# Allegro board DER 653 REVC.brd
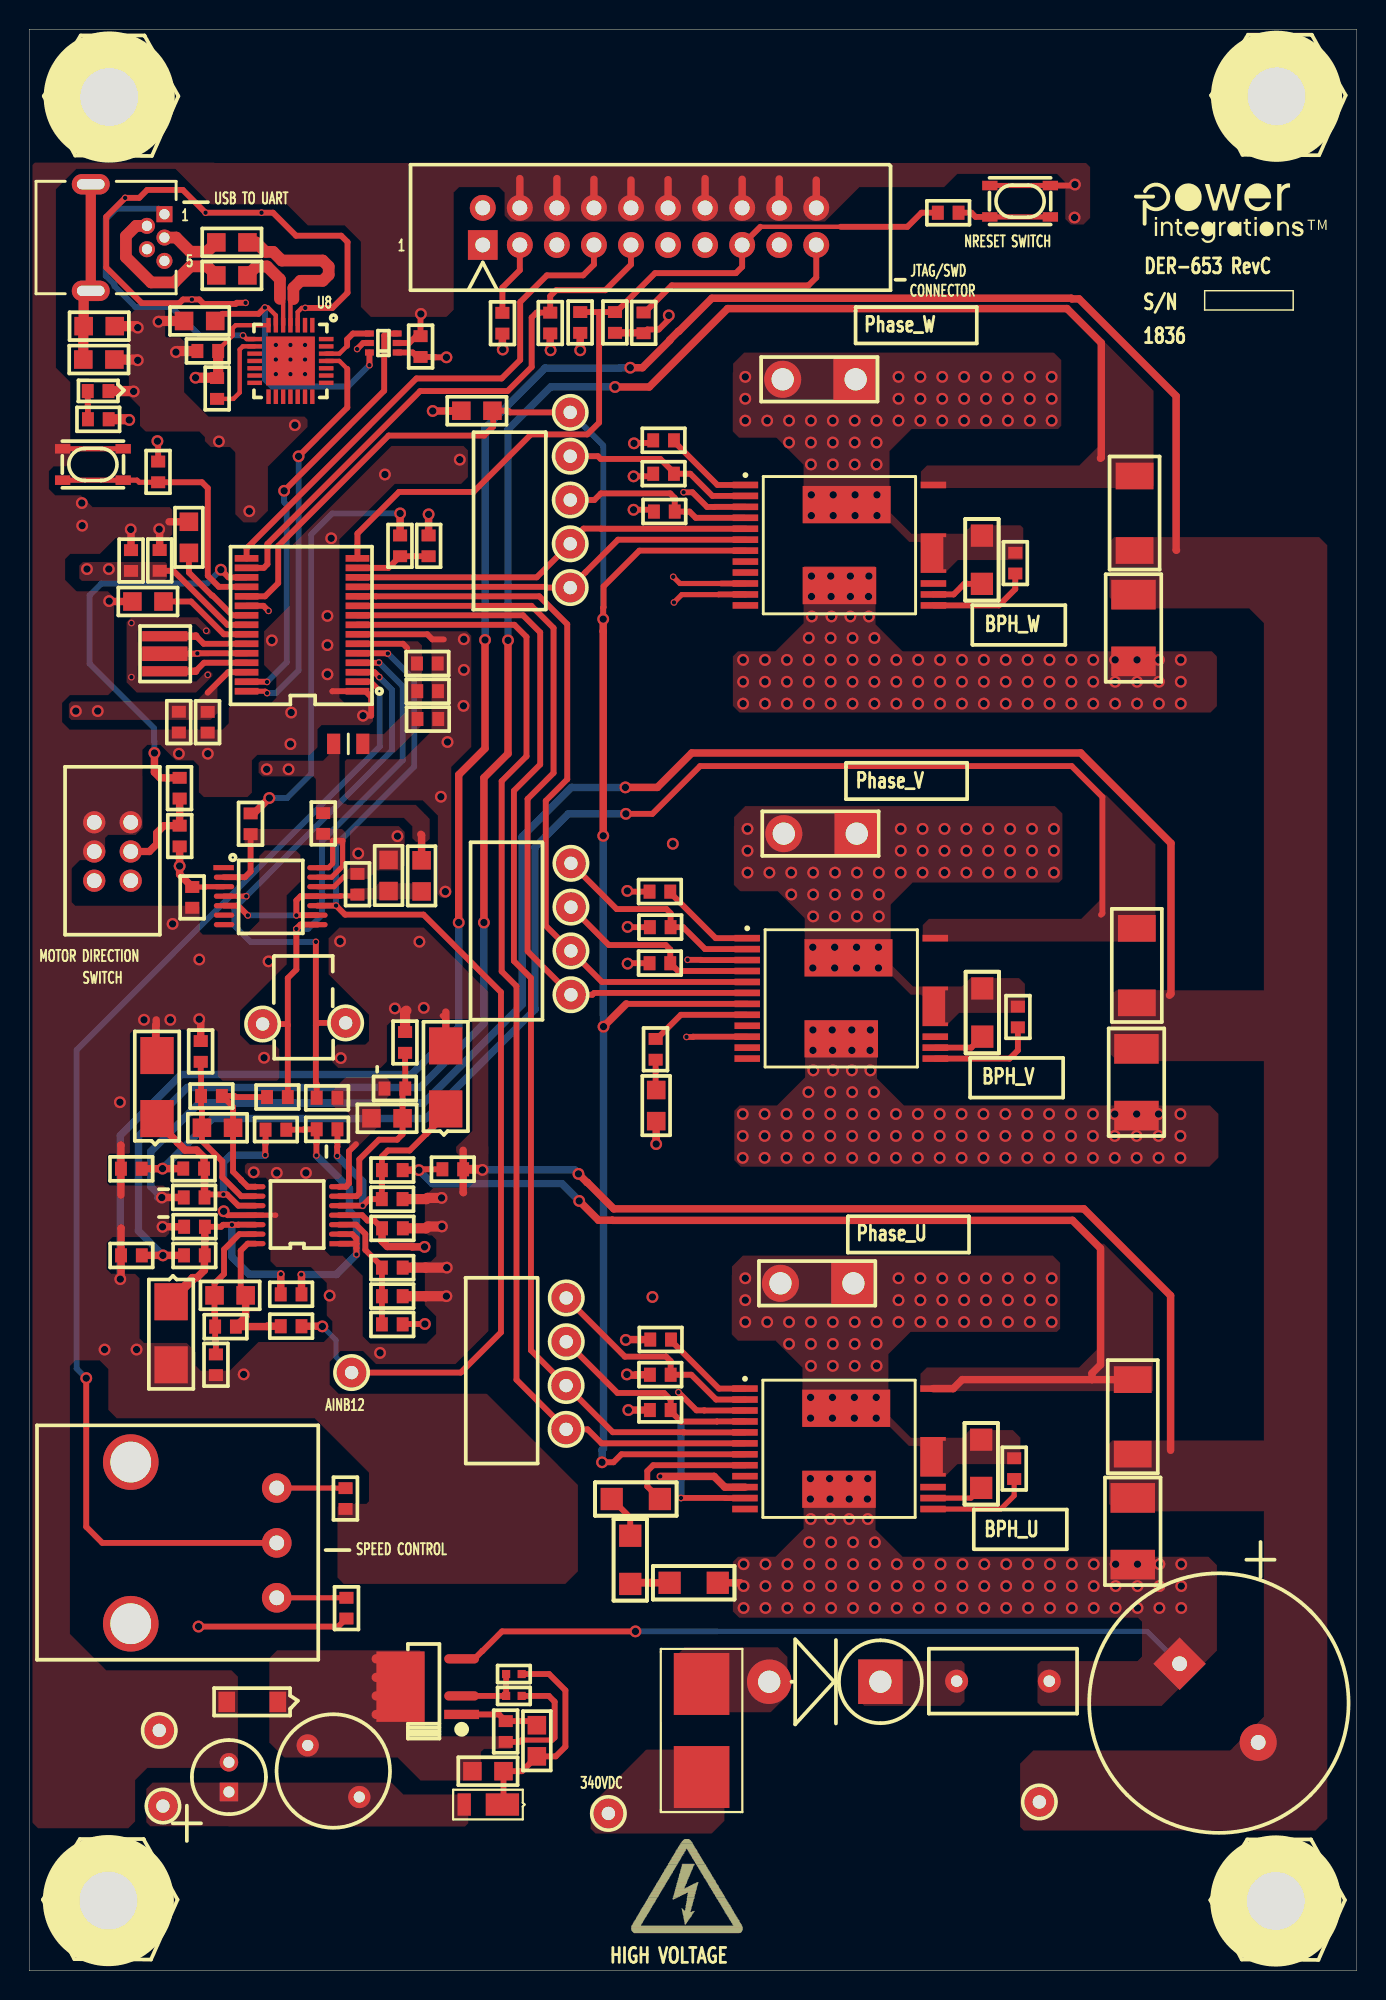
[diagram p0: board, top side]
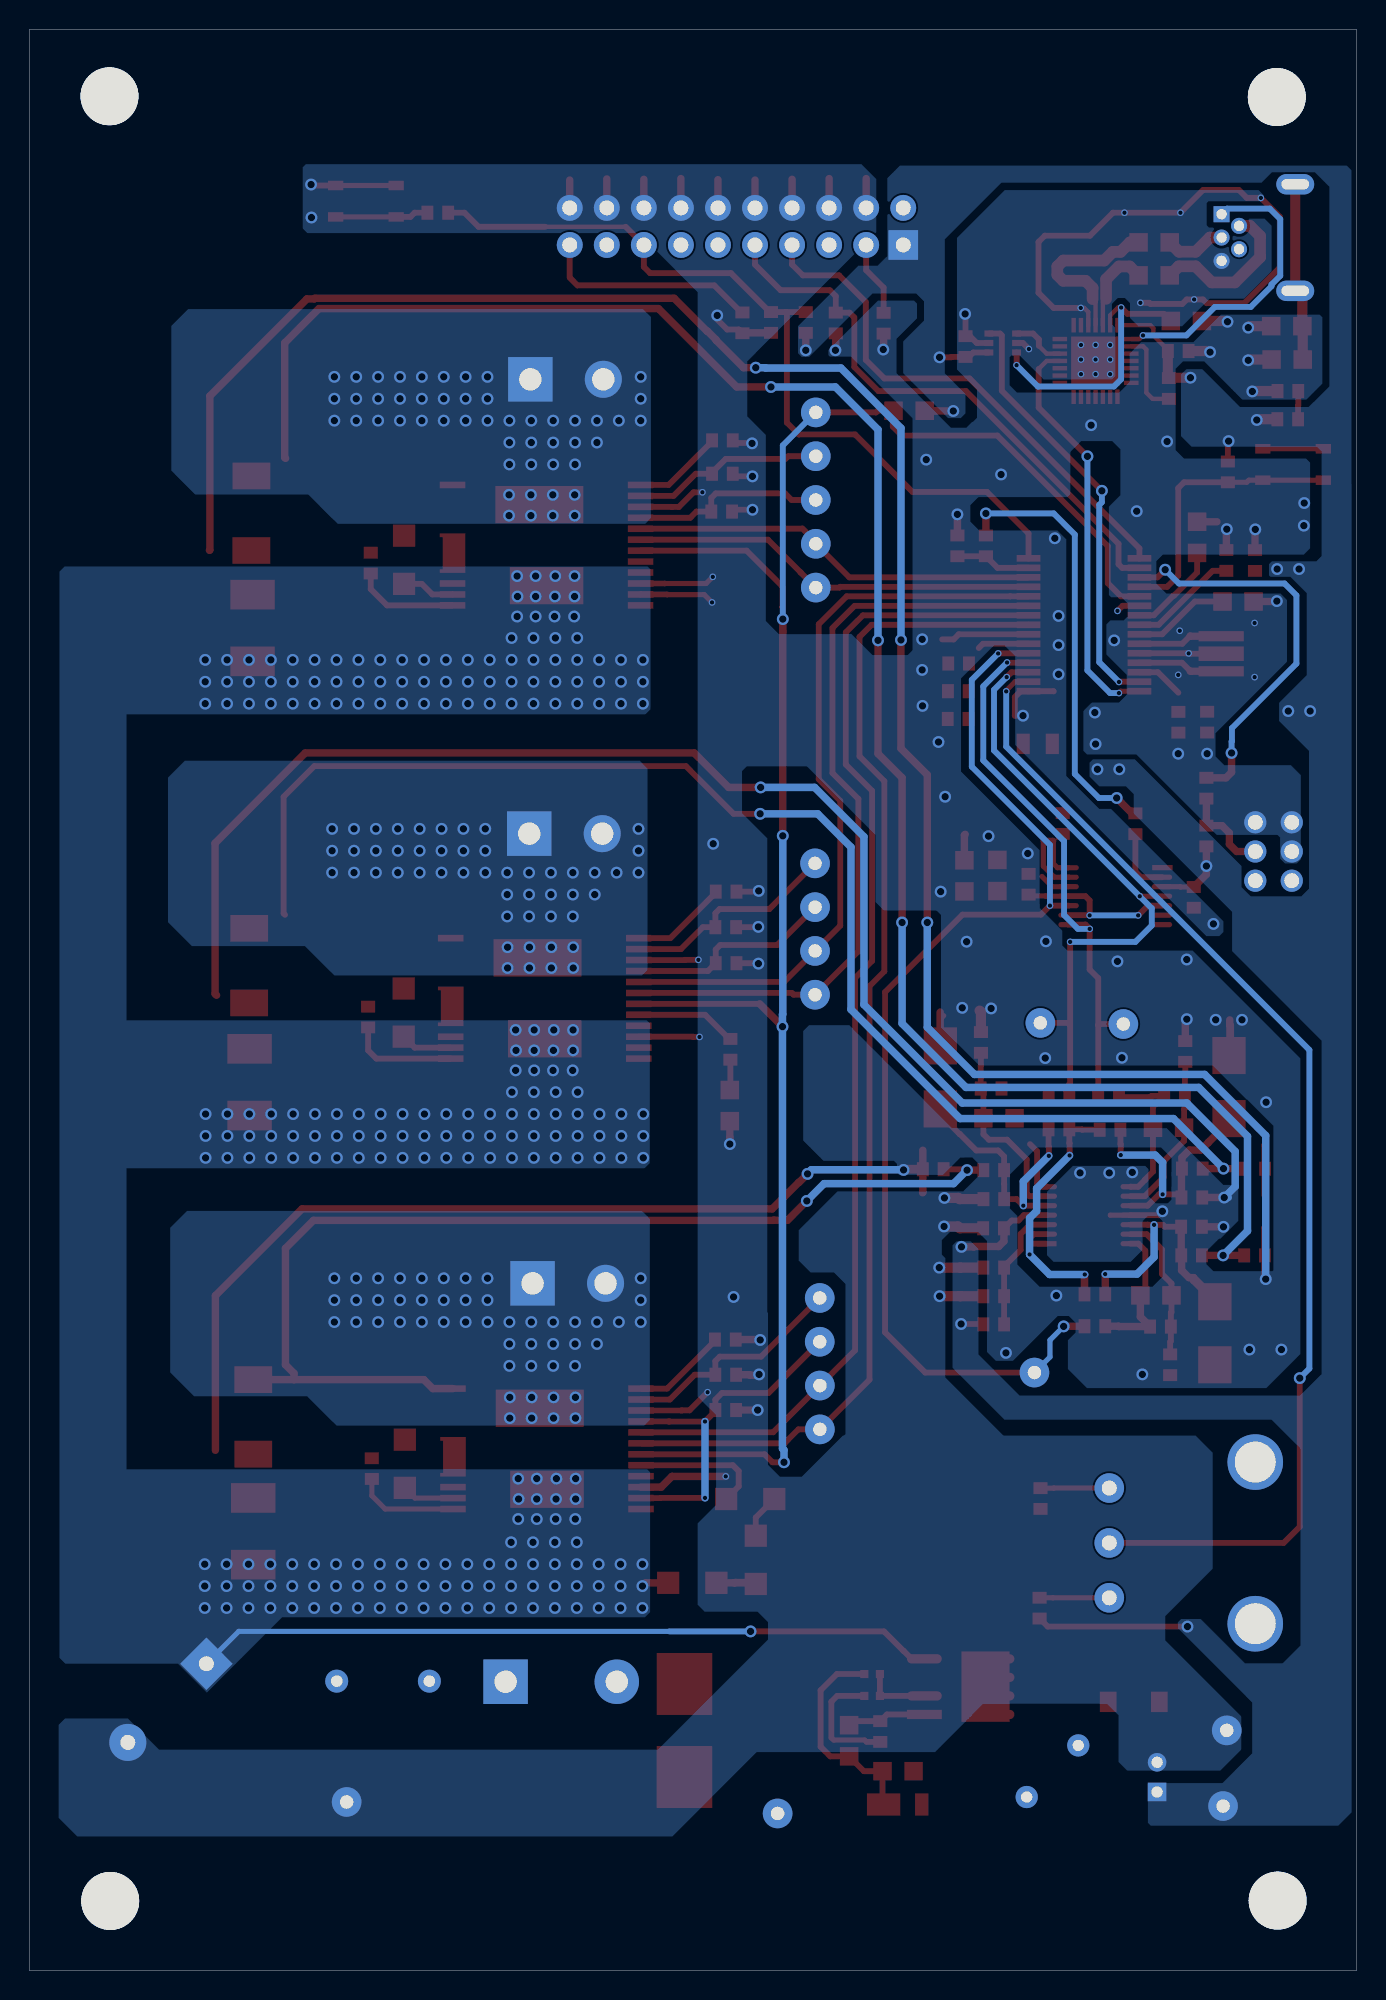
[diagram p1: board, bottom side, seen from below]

Outline 91 x 133 mm; copper layers: TOP, BOTTOM. Coordinates in mm from the lower left corner of the outline.
Outline path: 0,133 91,133 91,0 0,0 0,133

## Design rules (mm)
constraint set DEFAULT: min track width 0.35

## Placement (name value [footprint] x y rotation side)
AINB10  CON1  [PI_MILLMAX030D]  21.69 64.93 0 top
AINB11  CON1  [PI_MILLMAX030D]  16 64.85 0 top
AINB12  CON1  [PI_MILLMAX030D]  22.1 40.98 0 top
BPL_U  CON1  [PI_MILLMAX030D]  36.81 43.09 0 top
BPL_V  CON1  [PI_MILLMAX030D]  37.13 72.86 0 top
BPL_W  CON1  [PI_MILLMAX030D]  37.08 100.75 0 top
C1  100 pF  [PISMC0805]  23.46 58.4 0 top
C2  220 nF  [PISMC1812]  75.64 27.82 90 top
C3  4.7 uF  [PISMC1206]  65.25 33.08 90 top
C4  1000 pF  [PISMC0603]  29.75 54.9 180 top
C5  470 pF  [PISMC0603]  24.17 52.86 0 top
C6  1 nF  [PISMC0603]  8.94 95.9 90 top
C7  100 nF  [PISMC0603]  6.98 95.89 90 top
C8  100 pF  [PISMC0805]  13.97 57.75 180 top
C9  4.7uF  [PISMC0603]  26.62 85.75 0 top
C10  1 nF  [PISMC0603]  26.58 89.55 0 top
C11  100 nF  [PISMC0603]  26.6 87.65 0 top
C12  4.7 uF  [PISMC0805]  9.21 93.8 180 top
C13  1 nF  [PISMC0603]  12.23 86.24 270 top
C14  100 nF  [PISMC0603]  10.26 86.25 270 top
C15  1000 pF  [PISMC0603]  6.29 54.94 0 top
C16  1 uF  [PISMC0603]  43.97 38.41 180 top
C17  4.7 uF  [PISMC0805]  10.95 97.13 90 top
C18  470 pF  [PISMC0603]  12.02 52.97 180 top
C19  10 nF  [PISMC0603]  27.38 96.9 90 top
C20  100 pF  [PISMC0805]  14.84 46.27 180 top
C21  220 nF  [PISMC1812]  75.69 89.7 90 top
C22  4.7 uF  [PISMC1206]  65.33 63.99 90 top
C23  1000 pF  [PISMC0603]  6.3 49.01 0 top
C24  47 uF  [PIPOLCAPCLYD710LS300040]  78.85 21.03 315 top
C25  470 pF  [PISMC0603]  12.04 50.97 180 top
C26  1 uF  [PISMC0603]  43.94 69.02 180 top
C27  100 nF  [PISMC0603]  40.15 113.62 270 top
C28  1 uF  [PISMC0603]  24.18 48.17 0 top
C29  100 nF  [PISMC0603]  32.66 17.1 270 top
C30  10 uF  [PISMC0805]  32.51 13.67 180 top
C31  100 nF  [PISMC0603]  24.19 50.86 0 top
C32  220 nF  [PISMC1812]  75.9 58.58 90 top
C33  100 uF  [PIPOLCAPCLYD200LS80030]  13.69 12.25 90 top
C34  4.7 uF  [PISMC1206]  65.3 95 90 top
C35  100 nF  [PISMC0603]  11.18 74.24 270 top
C36  1 uF  [PISMC0603]  44.25 99.96 180 top
C37  4.7 uF  [PISMC0805]  3.73 112.66 0 top
C38  100 nF  [PISMC0603]  26.82 110.55 90 top
C39  4.7 uF  [PISMC0805]  10.62 113.01 0 top
C40  1 uF  [PISMC0603]  12.95 110.96 180 top
C41  1 uF  [PISMC0603]  22.5 73.72 90 top
D1  Green  [PI_SM_D_0603]  5.44 108.21 180 top
D2  SS13-E3/61T  [PISMDO214AC12]  28.55 59.04 90 top
D3  SS13-E3/61T  [PISMDO214AC12]  8.76 58.38 90 top
D4  1N5404-E3/54  [PIDV300X200X060DO15D0201AD]  58.34 19.8 180 top
D5  SS13-E3/61T  [PISMDO214AC12]  9.73 45.83 270 top
D6  DFLR1600-7  [PISMDDFLR120012]  32.46 11.39 0 top
D7  UFM15PL-TP  [PI_SM_SOD-123_12]  17.04 18.42 180 top
F1  Fuse Holder  [FUSE_E]  46.09 16.46 90 top
FAULT  CON1  [PI_MILLMAX030D]  37.08 106.75 0 top
GND  CON1  [PI_MILLMAX030D]  8.92 16.47 0 top
INH_U  CON1  [PI_MILLMAX030D]  36.8 37.09 0 top
INH_V  CON1  [PI_MILLMAX030D]  37.13 66.86 0 top
INH_W  CON1  [PI_MILLMAX030D]  37.08 94.75 0 top
INL_U  CON1  [PI_MILLMAX030D]  36.8 40.09 0 top
INL_V  CON1  [PI_MILLMAX030D]  37.13 69.86 0 top
INL_W  CON1  [PI_MILLMAX030D]  37.08 97.75 0 top
IPH_U  CON1  [PI_MILLMAX030D]  36.81 46.09 0 top
IPH_V  CON1  [PI_MILLMAX030D]  37.13 75.86 0 top
IPH_W  CON1  [PI_MILLMAX030D]  37.08 103.75 0 top
J1  CON2  [PI_CONN_QC_TAB_2PIN_LS200]  56.5 47.09 90 top
J2  CON2  [PI_CONN_QC_TAB_2PIN_LS200]  56.72 77.9 90 top
J3  CON2  [PI_CONN_QC_TAB_2PIN_LS200]  56.65 109.02 90 top
J4  CON20  [PI_20P_2X10_SHROUDED]  31.09 118.22 0 top
L1  220 Ohm@100MHz  [INDC2012X105N]  21.87 84.04 0 top
L2  680 uH  [PICHOKETOKINVD345H453LS197D030]  19.09 15.44 315 top
NOREF  -  []  91 0 90 top
NOREF#2  -  []  0 133 0 top
NOREF#3  -  []  -250.6 -129.63 0 top
NOREF#4  -  []  75.74 122.92 0 top
NOREF#5  -  []  -172.78 69.38 0 top
P1  CON5  [TE_CONNECTIVITY_1734510-1]  9.27 120.33 270 top
PGND  CON1  [PI_MILLMAX030D]  69.24 11.57 0 top
POST-CRKT_BRD_6-32_HEX1  Post Hex, 6-32, snap, 0.375L, NYL  [PIMTGHOLED156]  5.49 128.35 0 top
POST-CRKT_BRD_6-32_HEX2  Post Hex, 6-32, snap, 0.375L, NYL  [PIMTGHOLED156]  85.5 128.41 0 top
POST-CRKT_BRD_6-32_HEX3  Post Hex, 6-32, snap, 0.375L, NYL  [PIMTGHOLED156]  5.43 4.81 0 top
POST-CRKT_BRD_6-32_HEX4  Post Hex, 6-32, snap, 0.375L, NYL  [PIMTGHOLED156]  85.45 4.78 0 top
R1  330  [PISMR0603]  21.74 24.13 90 top
R2  4.99 k  [PISMR0805]  29.62 106.86 0 top
R3  1 k  [PISMR0603]  4.03 106.28 0 top
R4  22 k  [PISMR0603]  10.31 77.02 90 top
R5  3 M  [PISMR1206]  47.2 26.58 180 top
R6  10 k  [PI_VRES_VERTADJ]  16.97 25.55 90 top
R7  1 k  [PISMR0603]  25.78 60.43 180 top
R8  2.00 M  [PISMR1206]  41.2 29.8 270 top
R9  100  [PISMR0603]  10.31 81.72 270 top
R10  100  [PISMR0603]  19.71 59.8 0 top
R11  1 k  [PISMR0603]  25.76 64.3 270 top
R12  1 k  [PISMR0603]  25.6 54.85 180 top
R13  2.00 M  [PISMR1206]  43.23 32.32 180 top
R14  330  [PISMR0603]  21.68 33.06 270 top
R15  44.2 k  [PISMR0603]  67.51 33.69 90 top
R16  1 k  [PISMR0603]  19.71 57.64 0 top
R17  1 k  [PISMR0603]  11.78 59.93 0 top
R18  10 k  [PISMR0603]  43.97 40.83 180 top
R19  100  [PISMR0603]  17.73 59.85 180 top
R20  1 k  [PISMR0603]  11.76 63.69 270 top
R21  44.2 k  [PISMR0603]  43.99 43.24 180 top
R22  0.22  [PISMR2010]  75.64 40.5 270 top
R23  1 k  [PISMR0603]  10.56 54.95 0 top
R24  1 k  [PISMR0603]  25.42 98.32 270 top
R25  1 k  [PISMR0603]  17.62 57.61 180 top
R26  1 k  [PISMR0603]  12.75 44.13 0 top
R27  100  [PISMR0603]  18.67 44.15 180 top
R28  1 k  [PISMR0603]  12.8 40.8 90 top
R29  10 k  [PISMR0603]  32.44 112.15 90 top
R30  1 k  [PISMR0603]  10.61 49.01 0 top
R31  44.2 k  [PISMR0603]  67.77 64.63 90 top
R32  1 k  [PISMR0603]  18.67 46.34 180 top
R33  10 k  [PISMR0603]  43.96 71.49 180 top
R34  10 k  [PISMR0603]  35.71 112.16 90 top
R35  10 k  [PISMR0603]  37.77 113.62 270 top
R36  4.75 k  [PISMR0805]  42.98 58.2 90 top
R37  1 k  [PISMR0603]  24.18 44.28 0 top
R38  100 k  [PISMR0805]  34.8 16.82 270 top
R39  44.2 k  [PISMR0603]  43.94 73.92 180 top
R40  0.22  [PISMR2010]  75.92 71.41 270 top
R41  100  [PISMR0603]  62.28 120.43 0 top
R42  3.48 k  [PISMR0402]  32.69 20.33 0 top
R43  1 k  [PISMR0603]  25.6 46.21 180 top
R44  2.49 k  [PISMR0402]  32.69 18.83 0 top
R45  10 k  [PISMR0603]  42.11 112.17 90 top
R46  44.2 k  [PISMR0603]  67.59 95.72 90 top
R47  1 k  [PISMR0603]  20.15 77.88 90 top
R48  24 k  [PISMR0805]  26.9 76.07 270 top
R49  10 k  [PISMR0603]  44.2 102.55 180 top
R50  10  [PISMR0603]  8.84 103.39 270 top
R51  22.1  [PISMR0805]  14.96 118.4 180 top
R52  1 M  [PISMR0805]  3.71 110.37 0 top
R53  44.2 k  [PISMR0603]  44.2 104.83 180 top
R54  0.22  [PISMR2010]  75.77 102.4 270 top
R55  22.1  [PISMR0805]  14.96 116.14 180 top
R56  10 k  [PISMR0603]  12.88 107.68 90 top
R57  56.2 k  [PISMR0805]  24.63 73.96 90 top
R58  100  [PISMR0603]  15.18 79.28 270 top
RT1  10  [PIRAD400X175LS250031]  63.57 19.84 0 top
RT2  100 k  [PISMR0603]  42.94 63.83 270 top
SW1  SPST  [PI_SWITCH_SKRPABE010]  67.92 121.22 180 top
SW2  SPST  [PI_SWITCH_SKRPABE010]  4.37 103.18 180 top
SW3  DPDT SLIDE  [PI_SWITCH_DPDT_SLIDE_EG2209]  6.96 78.67 270 top
U1  AD8648ARUZ  [PI_SM_14TSSOP]  21.25 49.81 90 top
U2  BRD1265C  [PI_IC_INSOP_24C]  49.06 39.88 0 top
U3  TMPM375FSDMG  [PI_SM_30_SSOP]  22.5 87.65 90 top
U4  BRD1265C  [PI_IC_INSOP_24C]  49.22 70.74 0 top
U5  LNK3204D  [PISMSO8DNSHORT5678]  29.64 17.56 90 top
U6  BRD1265C  [PI_IC_INSOP_24C]  49.09 101.78 0 top
U7  BA10339FV-E2  [PI_SM_14LSSOP]  13.36 75.56 270 top
U8  CP2102-GMR  [PI_SM_28-VFQFN_EP]  17.91 110.27 180 top
U9  SN74LVC1T45DCKR  [PI_SM_SOT_363]  25.22 110.85 90 top
UNK+5V  CON1  [PI_MILLMAX030D]  9.17 11.29 0 top
VBUS_IN  CON1  [PI_MILLMAX030D]  39.7 10.78 0 top
Y1  10.0000 MHz  [PI_IC_CER_RESONATOR]  9.3 90.22 90 top

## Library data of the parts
AINB10-AINB12 BPL_U BPL_V BPL_W FAULT GND INH_U INH_V INH_W INL_U INL_V INL_W IPH_U IPH_V IPH_W PGND UNK+5V VBUS_IN = Term_1Pin
C1 C3-C15 C17-C20 C22 C23 C25 C27-C31 C34 C35 C37-C41 = CAP NP
C2 C21 C32 = CAP NP: room: 1
C16 C26 C36 = CAP NP: alternate symbols: (pismc0603_1); room: 4
C24 C33 = CAP POL
D1 = LED
D2 D3 D5 = DIODE SCHOTTKY
D4 = DIODE: alternate symbols: (pidax800x225060do15do201ad,pidv300x200x060do14wbead)
D6 D7 = DIODE
F1 = FUSE
J1-J3 = CON2
J4 = CON20
L1 = INDUCTOR_BEAD
L2 = INDUCTOR
P1 = USB MINI B R/A DIP
POST-CRKT_BRD_6-32_HEX1-POST-CRKT_BRD_6-32_HEX4 = POST_CRKT_BRD_6-32_HEX
R1-R4 R7 R9-R12 R14-R43 R45-R58 = R
R5 R8 R13 = R: room: 4
R6 = POT
R44 = R: tolerance: 1%
RT1 = THERMISTOR: alternate symbols: (pirad400x175ls250040_h)
RT2 = THERMISTOR
SW1 SW2 = SW PUSHBUTTON-SPST_1-2_3-4
SW3 = SW SLIDE-DPDT
U1 = TL084_Hetero
U2 U4 U6 = BridgeSwitch_1265C
U3 = TMPM375FSDMG
U5 = LNK32XX_8C
U7 = Comparator_Quad_Hetero
U8 = CP2102-GMR
U9 = SN74LVC1T45DCKR
Y1 = CRYSTAL_RESONATOR

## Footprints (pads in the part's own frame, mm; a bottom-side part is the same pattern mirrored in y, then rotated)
FUSE_E
  rect 4.242x3.81 smd: 1(-3.186,0) 2(3.186,0)
INDC2012X105N
  rect 0.9x1.4 smd: 1(-1,0) 2(1,0)
PI_20P_2X10_SHROUDED
  rect 2.032x2.032 hole 1.016: 1(0,0)
  round 1.778 hole 1.016: 2(0,2.54) 3(2.54,0) 4(2.54,2.54) 5(5.08,0) 6(5.08,2.54) 7(7.62,0) 8(7.62,2.54) 9(10.16,0) 10(10.16,2.54) 11(12.7,0) 12(12.7,2.54) 13(15.24,0) 14(15.24,2.54) 15(17.78,0) 16(17.78,2.54) 17(20.32,0) 18(20.32,2.54) 19(22.86,0) 20(22.86,2.54)
PI_CONN_QC_TAB_2PIN_LS200
  rect 3.048x3.048 hole 1.524: 1(0,0)
  round 2.54 hole 1.524: 2(0,5.001)
PI_IC_CER_RESONATOR
  rect 0.7x3.1 smd: 1(-1.199,0) 3(1.201,0)
  rect 1x3.1 smd: 2(0.002,0)
PI_IC_INSOP_24C
  rect 1.75x0.45 smd: 1(0,0) 2(0,-0.75) 3(0,-1.5) 4(0,-2.25) 5(0,-3) 6(0,-3.75) 7(0,-4.5) 8(0,-5.25) 9(0,-6) 10(0,-6.75) 11(0,-7.5) 12(0,-8.25) 13(12.89,-8.25) 14(12.89,-7.5) 15(12.89,-6.75) 24(12.89,0)
  custom 0.438x0.438 smd: 16(12.89,-4.67)
  rect 6.03x2.555 smd: 19(6.94,-1.347)
  rect 5.04x2.545 smd: 25(6.445,-6.897)
PI_MILLMAX030D
  round 2.032 hole 0.914: 1(0,0)
PI_SM_14LSSOP
  rect 0.356x1.397 smd: 1(-0.005,-0.03)
  oval 0.356x1.397 smd: 2(0.65,0) 3(1.3,0) 4(1.95,0) 5(2.6,0) 6(3.25,0) 7(3.9,0) 8(3.9,6.4) 9(3.25,6.4) 10(2.6,6.4) 11(1.95,6.4) 12(1.3,6.4) 13(0.65,6.4) 14(0,6.4)
PI_SM_14TSSOP
  rect 0.356x1.397 smd: 1(-0.005,-0.03)
  oval 0.356x1.397 smd: 2(0.65,0) 3(1.3,0) 4(1.95,0) 5(2.6,0) 6(3.25,0) 7(3.9,0) 8(3.9,5.75) 9(3.25,5.75) 10(2.6,5.75) 11(1.95,5.75) 12(1.3,5.75) 13(0.65,5.75) 14(0,5.75)
PI_SM_28-VFQFN_EP
  rect 0.3x1 smd: 1(-1.5,-2.45) 2(-1,-2.45) 3(-0.5,-2.45) 4(0,-2.45) 5(0.5,-2.45) 6(1,-2.45) 7(1.5,-2.45) 15(1.5,2.45) 16(1,2.45) 17(0.5,2.45) 18(0,2.45) 19(-0.5,2.45) 20(-1,2.45) 21(-1.5,2.45)
  rect 1x0.3 smd: 8(2.45,-1.5) 9(2.45,-1) 10(2.45,-0.5) 11(2.45,0) 12(2.45,0.5) 13(2.45,1) 14(2.45,1.5) 22(-2.45,1.5) 23(-2.45,1) 24(-2.45,0.5) 25(-2.45,0) 26(-2.45,-0.5) 27(-2.45,-1) 28(-2.45,-1.5)
  rect 3.35x3.35 smd: 29(0,0)
PI_SM_30_SSOP
  rect 0.457x1.626 smd: 1(0,0) 2(0.65,0) 3(1.3,0) 4(1.949,0) 5(2.599,0) 6(3.249,0) 7(3.899,0) 8(4.549,0) 9(5.199,0) 10(5.848,0) 11(6.5,0) 12(7.15,0) 13(7.8,0) 14(8.45,0) 15(9.1,0) 16(9.1,7.6) 17(8.45,7.6) 18(7.8,7.6) 19(7.15,7.6) 20(6.5,7.6) 21(5.85,7.6) 22(5.2,7.6) 23(4.55,7.6) 24(3.9,7.6) 25(3.25,7.6) 26(2.6,7.6) 27(1.95,7.6) 28(1.3,7.6) 29(0.65,7.6) 30(0,7.6)
PI_SM_D_0603
  rect 0.813x0.965 smd: 1(0,0) 2(1.422,0)
PI_SM_SOD-123_12
  rect 1.143x1.397 smd: 1(0,0) 2(3.505,0)
PI_SM_SOT_363
  rect 0.42x0.61 smd: 1(0,0) 2(0.65,0) 3(1.3,0) 4(1.3,1.9) 5(0.65,1.9) 6(0,1.9)
PI_SWITCH_DPDT_SLIDE_EG2209
  round 1.524 hole 1.016: 1(0,0) 2(2,0) 3(4,0) 4(0,-2.5) 5(2,-2.5) 6(4,-2.5)
PI_SWITCH_SKRPABE010
  rect 1.05x0.65 smd: 1(-2.075,1.075) 2(2.075,1.075) 3(-2.075,-1.075) 4(2.075,-1.075)
PI_VRES_VERTADJ
  round 3.81 hole 2.794: (-1.778,10.008) (9.296,10.008)
  round 2.032 hole 1.016: 1(0,0) 2(3.759,0) 3(7.518,0)
PICHOKETOKINVD345H453LS197D030
  round 1.524 hole 0.762: 1(0,0) 2(5,0)
PIDV300X200X060DO15D0201AD
  rect 3.048x3.048 hole 1.524: 1(0,0)
  round 3.048 hole 1.524: 2(7.62,0)
PIMTGHOLED156
  round 3.962 hole 3.962: 1(0,0)
PIPOLCAPCLYD200LS80030
  rect 1.27x1.27 hole 0.762: 1(0,0)
  round 1.27 hole 0.762: 2(2.032,0)
PIPOLCAPCLYD710LS300040
  rect 2.54x2.54 hole 1.016: 1(0,0)
  round 2.54 hole 1.016: 2(7.62,0)
PIRAD400X175LS250031
  round 1.575 hole 0.787: 1(0,0) 2(6.35,0)
PISMC0603
  rect 0.813x0.965 smd: 1(0,0) 2(1.422,0)
PISMC0805
  rect 1.27x1.27 smd: 1(0,0) 2(2.134,0)
PISMC1206
  rect 1.524x1.524 smd: 1(0,0) 2(3.302,0)
PISMC1812
  rect 2.032x3.048 smd: 1(0,0) 2(4.572,0)
PISMDDFLR120012
  rect 2.286x1.524 smd: 1(-0.025,0)
  rect 0.914x1.524 smd: 2(-2.642,0)
PISMDO214AC12
  rect 2.54x2.286 smd: 1(0,0) 2(4.318,0)
PISMR0402
  rect 0.559x0.559 smd: 1(0,0) 2(1.067,0)
PISMR0603
  rect 0.813x0.965 smd: 1(0,0) 2(1.422,0)
PISMR0805
  rect 1.27x1.27 smd: 1(0,0) 2(2.134,0)
PISMR1206
  rect 1.524x1.524 smd: 1(0,0) 2(3.302,0)
PISMR2010
  rect 1.829x2.591 smd: 1(0,0) 2(5.105,0)
PISMSO8DNSHORT5678
  rect 0.635x2.388 smd: 1(0,0)
  oval 0.635x2.388 smd: 2(1.27,0) 4(3.81,0) 5(3.81,4.978) 6(2.54,4.978) 7(1.27,4.978) 8(0,4.978)
TE_CONNECTIVITY_1734510-1
  rect 1.1x1.1 hole 0.7: 1(0,0)
  round 1.1 hole 0.7: 2(0.8,-1.2) 3(1.6,0) 4(2.4,-1.2) 5(3.2,0)
  oval 1.4x2.6 hole 0.7x1.9: 6(-2.05,-5.05) 7(5.25,-5.05)

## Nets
+3.3V: C39.2 U8.6 U9.6(VCCB)
+5V: C6.1 C7.1 C13.1 C14.1 C31.1 C33.1 C35.1 C38.1 C40.1 D6.2 J4.1 L1.1 L2.2 R1.1 R2.1 R3.2 R4.1 R35.2 R37.2 R47.2 R48.1 R50.1 R56.2 U1.4 U3.23 U3.28 U7.3 U8.7(VREGIN) U9.1 UNK+5V.1
GND: C2.2 C4.1 C5.2 C6.2 C7.2 C9.2 C10.2 C11.2 C12.2 C13.2 C14.2 C15.1 C16.2 C17.2 C18.2 C19.2 C21.2 C23.1 C24.2 C25.2 C26.2 C27.2 C28.2 C31.2 C32.2 C33.2 C35.2 C36.2 C37.2 C38.2 C39.1 C40.2 C41.2 D1.1(CATHODE) D2.2 D3.2 D5.2 D7.2 GND.1 J4.4 J4.6 J4.8 J4.10 J4.12 J4.14 J4.16 J4.18 J4.20 P1.5 PGND.1 R11.1 R14.2 R18.2 R20.1 R21.2 R22.2 R28.1 R29.1 R33.2 R34.1 R36.1 R39.2 R40.2 R43.1 R45.1 R49.2 R52.2 R53.2 R54.2 R57.2 SW1.3 SW1.4 SW2.3 SW2.4 SW3.1 SW3.4 SW3.5 U1.11 U2.3 U2.10 U3.1 U3.7 U3.26 U4.3 U4.10 U6.3 U6.10 U6.11 U7.12 U8.3 U8.29 U9.2 U9.5 Y1.2
V0: INH_V.1 U3.10 U4.6
VBUS: C2.1 C21.1 C24.1 C32.1 R5.1 RT1.2 U2.25 U4.25 U5.4 U6.25
VBUS IN: F1.1 VBUS_IN.1
AINB9: R6.2(WIPER) U3.2
AINB10: AINB10.1 R10.1 U3.3 U7.4
AINB11: AINB11.1 R19.1 U3.4 U7.8
AINB12: AINB12.1 R27.1 U3.5 U7.10
D+: R51.1 U8.4
D-: R55.1 U8.5
DMINUS: P1.2 R55.2
DPLUS: P1.3 R51.2
FAULT: FAULT.1 R2.2 U2.7 U3.20 U4.7 U6.7
ISENSE1: C4.2 R12.1 R22.1 U2.24
ISENSE2: C15.2 R23.1 R40.1 U4.24
ISENSE3: C23.2 R30.1 R54.1 U6.24
NEMG/NOVV: R24.1 R58.1
NRESET: C27.1 J4.15 R35.1 R41.1 U3.15
PB5/TDO/SWV: R9.1 U3.18
PB6/TDI/RXD1: R50.2 SW2.1 SW2.2 U3.19
PE0/TXD0: U3.30 U8.25
PE1/RXD0: U3.29 U9.3
PE2/SCLK0: U3.21
PHASEU: C3.2 J1.1 J1.2 R15.2 U2.16 U2.19
PHASEV: C22.2 J2.1 J2.2 R31.2 U4.16 U4.19
PHASEW: C34.2 J3.1 J3.2 R46.2 U6.16 U6.19
SOURCE: C29.2 C30.2 D7.1 L2.1 R44.2 U5.5(S) U5.6 U5.7 U5.8
TCK/SWCLK: J4.9 R34.2 U3.17
TMS/SWDIO: J4.7 U3.16
U0: INH_U.1 U2.6 U3.8
VREF: R16.1 R25.1 R32.1 U1.1 U1.2
W0: INH_W.1 U3.12 U6.6
X0: INL_U.1 U2.5 U3.9
Y0: INL_V.1 U3.11 U4.5
Z0: INL_W.1 U3.13(Z0/PG5) U6.5
N11220086: C19.1 R24.2 U3.14
N11227943: C9.1 C10.1 C11.1 L1.2 U3.6
N11232120: U3.27 Y1.1
N11232225: U3.25 Y1.3
N11232827: C17.1 U3.22
N11233445: C12.1 U3.24
N11251291: D1.2 R3.1
N11255215: R4.2 R9.2 SW3.2
N11983160: R1.2 R6.1
N11983204: R6.3 R14.1
N11990346: J4.3 R29.2
N11990582: J4.19 R45.2
N12027525: C3.1 U2.14
N12027529: R15.1 U2.13
N12027579: R8.1 R13.2
N12027695: IPH_U.1 R18.1 U2.2
N12027757: BPL_U.1 C16.1 U2.4 U2.11
N12027769: R21.1 U2.1(XL)
N12027985: RT2.1 U4.8
N12028197: C22.1 U4.14
N12028205: R31.1 U4.13
N12028339: IPH_V.1 R33.1 U4.2
N12028369: BPL_V.1 C26.1 U4.4
N12028389: R39.1 U4.1(XL)
N12028721: C34.1 U6.14
N12028725: R46.1 U6.13
N12028855: IPH_W.1 R49.1 U6.2
N12028877: BPL_W.1 C36.1 U6.4
N12028909: R53.1 U6.1(XL)
N12056627: R13.1 U2.8
N12134803: C1.1 R7.2 R10.2 U1.7
N12134815: C1.2 R7.1 R11.2 U1.6
N12135029: C5.1 D2.1 R12.2 R16.2 U1.5
N12135163: C8.1 R17.2 R19.2 U1.8
N12135175: C8.2 R17.1 R20.2 U1.9
N12135393: C18.1 D3.1 R23.2 R25.2 U1.10
N12135507: C20.1 R26.2 R27.2 U1.14(4OUT)
N12135519: C20.2 R26.1 R28.2 U1.13
N12135733: C25.1 D5.1 R30.2 R32.2 U1.12
N12135901: C28.1 R37.1 R43.2 U1.3
N12173083: C41.1 R48.2 R57.1 U7.5 U7.9 U7.11
N12173113: R47.1 R58.2 U7.2 U7.13(4OUT) U7.14
N12190188: R5.2 R8.2
N12206798: C29.1 R38.1 U5.1
N12206810: C30.1 D6.1 R38.2 R42.2
N12206840: R42.1 R44.1 U5.2
N12208110: D4.2 F1.2
N12208114: D4.1 RT1.1
N12209410: C37.1 P1.6 P1.7 R52.1
N12209768: P1.1(VBUS) U8.8
N12209854: U8.26 U9.4
N12210084: R56.1 U8.9
N12217120: R41.2 SW1.1 SW1.2
N12236869: R36.2 RT2.2
N12258817: SW3.6

Pads without a net: J4 2 5 11 13 17; P1 4; POST-CRKT_BRD_6-32_HEX1 1; POST-CRKT_BRD_6-32_HEX2 1; POST-CRKT_BRD_6-32_HEX3 1; POST-CRKT_BRD_6-32_HEX4 1; SW3 3; U2 9 12 15; U4 9 11 12 15; U6 8 9 12 15; U7 1 6 7; U8 1 2 10 11 12 13 14 15 16 17 18 19 20 21 22 23 24 27 28

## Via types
v1: diameter 0.457, hole 0.305, TOP to BOTTOM, 55 vias
v2: diameter 0.813, hole 0.508, TOP to BOTTOM, 511 vias

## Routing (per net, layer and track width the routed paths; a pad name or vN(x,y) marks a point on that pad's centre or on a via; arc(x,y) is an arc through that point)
+3.3V: length 19.2
  TOP w0.3: U8.6 16.91,113.39 16.37,113.93 v1(16.15,113.93)
  TOP w0.4: C39.2 13.24,113.5 15.73,113.5 v1(16.15,113.93) ; U9.6 v1(23.32,109.99)
  BOTTOM w0.4: v1(23.32,109.99) 21.86,108.52 16.65,108.52 16.15,109.02 v1(16.15,113.93)
+5V: length 54.4
  TOP w0.3: U8.7 14.16,112.72 13.94,112.51 13.94,112.02 12.95,111.03 C40.1
  TOP w0.35: C35.1 12.09,74.24 12.11,74.26 U7.3
  TOP w0.4: v2(28.6,110.52) 27.82,110.52 27.79,110.55 C38.1 26.59,110.55 26.29,110.85 U9.1 ; C6.1 9.88,95.9 13.58,92.2 U3.23 ; 12.23,87.55 13.63,88.95 U3.28 ; v2(27.12,44.31) 25.62,44.31 R37.2 ; R1.1 21.73,24.13 21.18,23.58 v2(11.61,23.58) ; v2(8.79,104.78) 8.84,104.73 R50.1 ; C31.1 23.66,51.39 23.19,51.39 22.82,51.76 U1.4
  TOP w0.508: v2(27.66,106.85) 28.88,106.85 28.9,106.87 29.62,106.87 R2.1 ; R35.2 v2(37.77,111.01) ; C31.1 24.19,49.97 24.55,49.62 26.23,49.62 26.26,49.59 v2(27.1,49.59) ; 26.84,77.85 26.9,77.8 R48.1 ; C35.1 10.31,75.1 v2(10.31,75.68) R4.1
  TOP w0.7: R3.2 6.81,106.28 v2(6.86,106.23) ; v2(11.4,109.13) 12.85,109.13 R56.2 12.95,109.18 C40.1
  vias: v2(3.2,86.29) v2(3.96,96.02) v2(4.7,86.29) v2(5.46,96.02) v2(16.28,82.3) v2(17.78,82.3)
GND: length 514.2
  TOP w0.3: U8.3 18.41,113.63 18.68,113.91 v1(18.92,113.91)
  TOP w0.35: SW2.3 SW2.4 ; 8.71,64.8 8.76,64.74 D3.2 ; U7.12 20.88,74.26 21.59,74.97 ; D2.2 28.55,65.2 28.54,65.2 28.31,65.43 ; SW1.4 SW1.3 ; 47.28,94.28 47.26,94.27 44.73,94.27 v1(44.2,93.73) ; v1(44.15,95.49) 44.6,95.03 47.45,95.03 ; 16.89,51.76 16.89,51.76 U1.11 ; C26.2 42.52,69.1
  TOP w0.4: C36.2 42.7,100.08 41.43,100.08 v2(41.42,100.08) ; v2(13.33,52.03) 13.6,51.76 U1.11 ; v1(22.48,111.09) 22.89,111.5 U9.5 ; v2(41.02,68.99) 41.05,69.02 C26.2 ; v1(44.5,39.63) 45.74,38.39 46.28,38.39 46.29,38.38 U2.3 ; SW1.3 71.61,122.29 v2(71.68,122.36) ; 11.66,90.25 U3.26 ; 11.66,90.25 11.54,90.25 v1(11.53,90.24) ; 11.66,90.25 11.65,90.24 ; R49.2 42.6,102.37 41.43,102.37 v2(41.43,102.37) ; U9.2 26.05,111.5 26.52,111.97 C38.2 26.82,113.47 v2(26.85,113.5) ; 28.42,91.2 27.64,91.2 27.29,91.55 U3.7 ; v2(41.45,104.63) 41.48,104.66 42.6,104.66 R53.2 ; 71.61,120.14 v2(71.65,120.1) ; R33.2 41.04,71.49 v2(41.02,71.51) ; U6.11 47.28,94.28 ; v2(41,73.97) 41.05,73.92 R39.2 ; v1(14.83,114.26) 14.23,114.26 14.15,114.18 11.96,114.18 11.66,114.49 v1(11.15,114.49) 10.54,114.49 10.29,114.23 7.72,114.23 5.28,116.67 5.28,120.15 v1(6.58,121.45) 7.54,121.45 8.09,121.99 10.53,121.99 v1(12.09,120.43) v1(15.93,120.43) 16.71,120.43 18.29,118.86 21.39,118.86 21.82,118.42 21.82,114.94 20.78,113.91 v1(18.92,113.91) ; U6.3 46.95,100.28 46.94,100.28 46.47,100.28 45.46,101.28 v1(44.86,101.28) ; R45.1 42.37,112.43 43.15,112.43 43.84,113.11 v2(43.84,113.39) ; v1(45.13,69.25) 46.05,69.25 46.06,69.24 U4.3 ; v1(45.06,63.97) 45.48,63.97 45.5,63.99 U4.10 ; v2(22.88,85.98) 23.44,85.98 23.44,87.25 23.04,87.65 U3.1 20.79,87.65 20.78,87.64 ; Y1.2 11.4,90.22 11.42,90.24 ; 47.45,95.03 U6.10
  TOP w0.5: v2(41.07,38.41) 41.22,38.41 41.22,38.41 C16.2 ; R36.1 v2(42.98,56.63)
  TOP w0.508: R20.1 11.76,65.08 v2(11.65,65.19) ; C12.2 5.51,93.8 v2(5.48,93.82) ; J4.14 46.33,122.77 ; 29.75,56.21 C4.1 29.75,53.32 29.77,53.3 ; R21.2 40.92,43.24 v2(40.89,43.21) ; v2(8.91,98.75) 8.94,98.72 C6.2 ; v1(43.26,33.87) 46.94,33.87 47.68,33.13 U2.10 ; C17.2 9.59,99.26 ; 28.56,63.23 28.56,65.67 ; 42.98,57.13 v2(42.98,56.63) ; v2(6.96,98.74) 6.98,98.72 C7.2 ; v2(9.09,52.97) 9.1,52.97 C18.2 ; 10.26,83.37 v2(10.26,83.37) ; v2(6.24,47.38) 6.3,47.43 C23.1 6.3,50.87 6.3,50.87 ; J4.18 51.41,122.74 ; v2(41.2,109.81) 42.04,109.81 43.91,111.69 43.91,111.72 44.51,112.31 44.54,112.31 46.79,114.57 71.43,114.57 71.47,114.53 71.96,114.53 78.62,107.87 78.62,97.33 78.64,97.3 ; 12.23,83.38 v2(12.24,83.37) ; v2(40.97,40.85) 41.02,40.8 41.6,40.8 41.63,40.83 R18.2 ; v2(9.14,50.96) 9.15,50.97 C25.2 ; J4.10 41.25,122.67 ; v2(35.74,111.01) 35.71,111.03 R34.1 ; v2(40.86,81.06) 43.06,81.06 45.42,83.42 72.08,83.42 78.26,77.24 78.26,66.93 78.16,66.82 ; C27.2 42.09,112.2 R45.1 ; J4.4 33.63,122.77 ; v2(32.46,111.06) 32.44,111.08 R29.1 ; 8.71,65.13 8.71,64.8 8.67,64.76 8.67,62.7 ; v2(29.44,71.81) 29.44,81.93 31.24,83.73 v2(31.24,91.16) ; v2(37.65,54.59) 38.24,54 38.27,54 40.07,52.19 72.29,52.19 78.23,46.25 78.23,35.66 ; J4.20 53.95,122.67 ; 6.28,56.56 6.29,56.55 C15.1 6.29,53.14 ; v2(31.07,54.86) 31.07,54.89 ; J4.16 48.87,122.72 ; J4.12 43.79,122.69 ; J4.8 38.71,122.72 ; J4.6 36.17,122.77 ; C19.2 27.38,99.77 v2(27.38,99.77)
  TOP w0.6: C4.1 31.03,54.9 31.06,54.87
  TOP w0.7: v2(7.16,108.19) 7.14,108.21 D1.1 ; C31.2 27.21,50.86 27.34,50.99 v2(28.29,50.99) ; C39.1 8.92,113.01 v2(8.86,112.96) ; C37.2 7.34,112.66 v2(7.44,112.56) ; C40.2 10.13,110.96 v2(10.06,110.88) ; C28.2 27.18,48.17 27.19,48.17 v2(28.62,48.17) ; R52.2 7.39,110.37 v2(7.44,110.32) ; R11.1 25.76,65.68 25.85,65.77 ; R43.1 27.18,46.21 27.18,46.21 v2(28.6,46.21) ; C5.2 27.23,52.86 27.31,52.94 v2(28.27,52.94)
  BOTTOM w0.508: 31.06,54.87 37.39,54.87 37.65,54.62 v2(37.65,54.59) ; v2(29.44,71.81) 29.44,64.64 26.21,61.4 10.43,61.4 6.24,57.22 v2(6.24,47.38) ; v2(31.24,91.16) 31.24,105.68 35.36,109.79 40.51,109.79 40.54,109.81 v2(41.2,109.81) ; 8.82,52.97 v2(9.09,52.97) 8.33,53.72 8.33,56.12 11.65,59.44 27.04,59.44 33.78,66.18 33.78,77.68 37.16,81.06 v2(40.86,81.06)
  vias: v1(7.01,92.33) v1(7.01,88.62) v1(12.14,91.79) v1(12.24,88.77) v1(16.91,111.37) v1(16.91,110.37) v1(16.91,109.37) v1(17.91,111.37) v1(17.91,110.37) v1(17.91,109.37) v1(18.91,111.37) v1(18.91,110.37) v1(18.91,109.37) v2(3.61,100.54) v2(3.63,98.99) v2(5.17,42.55) v2(6.22,59.5) v2(7.36,42.55) v2(7.87,65.14) v2(9.67,65.14) v2(9.83,71.71) v2(11.66,69.27) v2(13,104.76) v2(14.7,40.85) v2(15.09,99.98) v2(15.39,54.69) v2(16.1,62.54) v2(16.41,69.15) v2(16.63,91.13) v2(16.97,54.66) v2(17.91,84.03) v2(17.96,86.19) v2(18.21,105.88) v2(18.97,54.66) v2(20.44,92.81) v2(20.44,90.81) v2(20.44,88.81) v2(20.6,46.25) v2(20.7,98.13) v2(21.31,70.52) v2(21.36,62.52) v2(22.56,76.54) v2(24.05,42.33) v2(24.38,102.5) v2(25.07,65.92) v2(25.24,77.72) v2(26.75,70.49) v2(27.05,65.96) v2(28.22,80.42) v2(28.52,73.92) v2(28.67,84.17) v2(29.51,103.51) v2(29.79,91.21) v2(29.79,89.11) v2(29.77,86.65) v2(42.72,46.16) v2(44.12,77.2)
V0: length 53.3
  TOP w0.4: U3.10 34.42,93.5 35.94,91.98 35.94,82.05 34.16,80.27 34.16,69.83 INH_V.1 38.6,66.86 38.73,66.99 U4.6
VBUS: length 52.8
  TOP w0.4: v2(41.55,23.25) 32.41,23.25 31.08,21.92 31.06,21.92 30.52,21.37 U5.4
  TOP w0.508: R5.1 48.74,26.58 v2(48.97,26.35)
  BOTTOM w0.35: 47.12,23.25 76.64,23.25 C24.1
  BOTTOM w0.4: 47.12,23.25 v2(41.55,23.25)
  vias: v2(48.93,89.8) v2(48.93,88.3) v2(48.93,86.8) v2(48.91,58.69) v2(48.91,57.19) v2(48.91,55.69) v2(48.97,27.85) v2(48.97,24.85) v2(50.43,89.8) v2(50.43,88.3) v2(50.43,86.8) v2(50.41,58.69) v2(50.41,57.19) v2(50.41,55.69) v2(50.47,27.85) v2(50.47,26.35) v2(50.47,24.85) v2(51.93,89.8) v2(51.93,88.3) v2(51.93,86.8) v2(51.91,58.69) v2(51.91,57.19) v2(51.91,55.69) v2(51.97,27.85) v2(51.97,26.35) v2(51.97,24.85) v2(53.43,91.3) v2(53.43,89.8) v2(53.43,88.3) v2(53.43,86.8) v2(53.41,60.19) v2(53.41,58.69) v2(53.41,57.19) v2(53.41,55.69) v2(53.54,33.71) v2(53.54,32.32) v2(53.47,29.35) v2(53.47,27.85) v2(53.47,26.35) v2(53.47,24.85) v2(53.62,95.54) v2(53.62,94.14) v2(53.64,92.77) v2(53.57,30.95) v2(53.72,64.45) v2(53.72,63.05) v2(53.75,61.68) v2(54.94,95.54) v2(54.93,91.3) v2(54.93,89.8) v2(54.93,88.3) v2(54.93,86.8) v2(54.91,60.19) v2(54.91,58.69) v2(54.91,57.19) v2(54.91,55.69) v2(54.86,33.71) v2(54.89,32.32) v2(54.91,30.95) v2(54.97,94.14) v2(54.99,92.77) v2(55.04,64.45) v2(54.97,29.35) v2(54.97,27.85) v2(54.97,26.35) v2(54.97,24.85) v2(55.07,63.05) v2(55.09,61.68) v2(56.21,33.71) v2(56.21,32.32) v2(56.21,30.95) v2(56.29,95.54) v2(56.29,94.14) v2(56.29,92.77) v2(56.43,91.3) v2(56.43,89.8) v2(56.43,88.3) v2(56.43,86.8) v2(56.39,64.45) v2(56.39,63.05) v2(56.39,61.68) v2(56.41,60.19) v2(56.41,58.69) v2(56.41,57.19) v2(56.41,55.69) v2(56.47,29.35) v2(56.47,27.85) v2(56.47,26.35) v2(56.47,24.85) v2(57.53,94.14) v2(57.48,33.71) v2(57.45,32.32) v2(57.48,30.95) v2(57.56,95.54) v2(57.56,92.77) v2(57.63,63.05) v2(57.66,64.45) v2(57.66,61.68) v2(57.93,91.3) v2(57.93,89.8) v2(57.93,88.3) v2(57.93,86.8) v2(57.91,60.19) v2(57.91,58.69) v2(57.91,57.19) v2(57.91,55.69) v2(57.97,29.35) v2(57.97,27.85) v2(57.97,26.35) v2(57.97,24.85) v2(59.43,89.8) v2(59.43,88.3) v2(59.43,86.8) v2(59.41,58.69) v2(59.41,57.19) v2(59.41,55.69) v2(59.47,27.85) v2(59.47,26.35) v2(59.47,24.85) v2(60.93,89.8) v2(60.93,88.3) v2(60.93,86.8) v2(60.91,58.69) v2(60.91,57.19) v2(60.91,55.69) v2(60.97,27.85) v2(60.97,26.35) v2(60.97,24.85) v2(62.43,89.8) v2(62.43,88.3) v2(62.43,86.8) v2(62.41,58.69) v2(62.41,57.19) v2(62.41,55.69) v2(62.47,27.85) v2(62.47,26.35) v2(62.47,24.85) v2(63.93,89.8) v2(63.93,88.3) v2(63.93,86.8) v2(63.91,58.69) v2(63.91,57.19) v2(63.91,55.69) v2(63.97,27.85) v2(63.97,26.35) v2(63.97,24.85) v2(65.43,89.8) v2(65.43,88.3) v2(65.43,86.8) v2(65.41,58.69) v2(65.41,57.19) v2(65.41,55.69) v2(65.47,27.85) v2(65.47,26.35) v2(65.47,24.85) v2(66.93,89.8) v2(66.93,88.3) v2(66.93,86.8) v2(66.91,58.69) v2(66.91,57.19) v2(66.91,55.69) v2(66.97,27.85) v2(66.97,26.35) v2(66.97,24.85) v2(68.43,89.8) v2(68.43,88.3) v2(68.43,86.8) v2(68.41,58.69) v2(68.41,57.19) v2(68.41,55.69) v2(68.47,27.85) v2(68.47,26.35) v2(68.47,24.85) v2(69.93,89.8) v2(69.93,88.3) v2(69.93,86.8) v2(69.91,58.69) v2(69.91,57.19) v2(69.91,55.69) v2(69.97,27.85) v2(69.97,26.35) v2(69.97,24.85) v2(71.43,89.8) v2(71.43,88.3) v2(71.43,86.8) v2(71.41,58.69) v2(71.41,57.19) v2(71.41,55.69) v2(71.47,27.85) v2(71.47,26.35) v2(71.47,24.85) v2(72.93,89.8) v2(72.93,88.3) v2(72.93,86.8) v2(72.91,58.69) v2(72.91,57.19) v2(72.91,55.69) v2(72.97,27.85) v2(72.97,26.35) v2(72.97,24.85) v2(74.43,89.8) v2(74.43,88.3) v2(74.43,86.8) v2(74.41,58.69) v2(74.41,57.19) v2(74.41,55.69) v2(74.47,27.85) v2(74.47,26.35) v2(74.47,24.85) v2(75.93,89.8) v2(75.93,88.3) v2(75.93,86.8) v2(75.91,58.69) v2(75.91,57.19) v2(75.91,55.69) v2(75.97,27.85) v2(75.97,26.35) v2(75.97,24.85) v2(77.43,89.8) v2(77.43,88.3) v2(77.43,86.8) v2(77.41,58.69) v2(77.41,57.19) v2(77.41,55.69) v2(77.47,27.85) v2(77.47,26.35) v2(77.47,24.85) v2(78.93,89.8) v2(78.93,88.3) v2(78.93,86.8) v2(78.91,58.69) v2(78.91,57.19) v2(78.91,55.69) v2(78.97,27.85) v2(78.97,26.35) v2(78.97,24.85)
AINB9: length 81.5
  TOP w0.35: v1(24.03,87.64) 24.03,87.69 23.42,88.3 U3.2
  TOP w0.4: v2(3.91,40.6) 3.91,30.41 5.01,29.31 R6.2
  BOTTOM w0.4: v2(3.91,40.6) 3.25,41.26 3.25,63.08 24.03,83.86 v1(24.03,87.64)
AINB10: length 43.9
  TOP w0.35: U7.4 14.75,73.61 14.75,73.61 v1(14.88,73.61)
  TOP w0.4: AINB10.1 19.8,64.93 19.65,64.78 ; 19.65,64.78 19.65,60.8 19.71,60.74 R10.1 ; 19.65,64.78 v1(19.65,70.48) ; U3.3 23.66,88.95 v1(24,88.62)
  BOTTOM w0.4: v1(19.65,70.48) 15.18,70.48 14.05,71.6 14.05,72.78 v1(14.88,73.61) 24.87,83.59 24.87,87.75 v1(24,88.62)
AINB11: length 39.4
  TOP w0.4: 17.73,64.78 17.73,68 18.31,68.59 18.31,71.37 18.6,71.66 ; 17.73,64.78 R19.1 ; 17.73,64.78 17.65,64.85 AINB11.1 ; 18.6,71.66 18.6,71.66 v1(18.31,71.37) ; 18.6,71.66 U7.8 ; v1(23.97,89.62) 23.96,89.6 U3.4
  BOTTOM w0.4: v1(18.31,71.37) 19.11,71.37 20.07,72.32 20.07,77.38 25.6,82.91 25.6,87.99 v1(23.97,89.62)
AINB12: length 77.5
  TOP w0.4: AINB12.1 29.58,40.98 32.34,43.73 32.34,67.04 27.03,72.35 21.65,72.35 v1(21.03,72.96) 21.03,72.96 U7.10 ; v1(24.58,90.24) 24.51,90.24 24.5,90.25 U3.5
  TOP w0.508: v2(20.09,44.14) 20.08,44.15 R27.1
  BOTTOM w0.35: v2(20.09,44.14) 21.03,43.2 21.03,42.05 AINB12.1
  BOTTOM w0.4: v1(24.58,90.24) 26.39,88.43 26.39,82.48 21.03,77.13 v1(21.03,72.96)
D+: length 12.2
  TOP w0.3: U8.4 17.91,114.31 18.11,114.51
  TOP w0.8: R51.1 15.54,118.4 16.2,117.75 16.72,117.75 17.31,117.15 20.12,117.15 20.53,116.75 20.53,116.17 20.12,115.77 18.6,115.77 18.11,115.28 18.11,114.51
D-: length 6.1
  TOP w0.3: 17.19,114.53 17.41,114.31 U8.5
  TOP w0.8: R55.1 15.57,116.75 16.31,116.75 17.19,115.87 17.19,114.53
DMINUS: length 10.8
  TOP w0.8: P1.2 7.33,119.53 6.63,118.83 6.63,117.38 8.36,115.65 9.95,115.65 11.05,116.76 12.21,116.76 R55.2
DPLUS: length 4.2
  TOP w0.8: P1.3 10.07,118.73 11.04,117.76 12.19,117.76 R51.2
FAULT: length 136.1
  TOP w0.4: U4.7 40.93,66.24 ; U6.7 41.82,97.28 39.37,94.83 39.37,93.4 39.34,93.38 v2(39.34,92.59) ; v2(39.26,34.84) 40.05,34.84 40.59,35.38 U2.7 ; FAULT.1 32.96,106.75 32.84,106.86 R2.2 31.8,106.81 31.8,105.78 31.19,105.16 24.64,105.16 17.07,97.6 17.07,95.05 16.17,94.15 U3.20
  TOP w0.508: 40.93,66.24 v2(39.37,64.67) ; v2(39.35,77.75) 39.35,91.75 39.34,91.75 v2(39.34,92.59)
  BOTTOM w0.4: FAULT.1 39.34,104.49 v2(39.34,92.59)
  BOTTOM w0.508: v2(39.35,77.75) 39.35,65.53 39.37,65.51 v2(39.37,64.67) 39.37,35.77 39.26,35.67 v2(39.26,34.84)
ISENSE1: length 74.9
  TOP w0.4: C4.2 26.77,54.9
  TOP w0.508: R22.1 72.85,40.5 ; 72.85,40.5 72.85,40.93 73.43,41.51 73.43,49.48 71.51,51.41 39.97,51.41 39.96,51.41 39.02,51.41 v2(37.7,52.74) ; 72.85,40.5 63.95,40.5 63.34,39.88 U2.24 ; 26.77,54.9 v2(26.72,54.85) R12.1
  BOTTOM w0.508: v2(37.7,52.74) 36.51,53.92 27.64,53.92 v2(26.72,54.85)
ISENSE2: length 94.2
  TOP w0.4: 73.47,72.34 73.56,72.43 73.56,80.41 71.45,82.52 45.99,82.52 42.72,79.25 v2(40.9,79.25)
  TOP w0.508: R23.1 9.14,54.95 v2(9.14,54.95) 9.13,54.94 C15.2
  BOTTOM w0.508: v2(40.9,79.25) 36.95,79.25 34.67,76.97 34.67,65.85 27.2,58.38 12.57,58.38 v2(9.14,54.95)
ISENSE3: length 133
  TOP w0.508: v2(40.16,108.49) 42.5,108.49 47.87,113.86 71.14,113.86 73.49,111.51 73.49,103.66 73.43,103.6 ; R30.1 9.17,49.01 v2(9.17,49.01) 9.16,49.01 C23.2 ; v2(32.82,91.14) 32.82,83.37 31.17,81.72 v2(31.17,71.81)
  BOTTOM w0.508: v2(32.82,91.14) 32.82,105.57 35.74,108.49 v2(40.16,108.49) ; v2(9.17,49.01) 7.49,50.68 7.49,57.17 10.84,60.51 26.79,60.51 31.17,64.89 v2(31.17,71.81)
NEMG/NOVV: length 29.9
  TOP w0.508: R24.1 25.42,99.83 v2(25.43,99.83) ; v2(16.46,80.34) 15.4,79.28 R58.1
  BOTTOM w0.4: v2(25.43,99.83) 20.78,99.83 19.33,98.38 19.33,81.99 17.68,80.34 v2(16.46,80.34)
NRESET: length 57.2
  TOP w0.3: 55.63,119.46 50.11,119.46
  TOP w0.4: R41.1 61.16,120.43 60.2,119.46 55.63,119.46 ; 39.11,113.62 R35.1 ; 39.11,113.62 39.11,113.62 C27.1 40.23,113.62 42.9,116.29 48.44,116.29 48.87,116.72 J4.15 50.11,119.46 ; 39.11,113.62 39.07,113.58 39.07,106.05 38.25,105.24 34.39,105.24 30.45,101.3 25.35,101.3 22.5,98.46 U3.15
PB5/TDO/SWV: length 27.5
  TOP w0.4: v2(13.14,95.97) 13.66,95.45 U3.18
  TOP w0.508: v2(8.59,83.42) 8.59,82.1 8.97,81.72 R9.1
  BOTTOM w0.4: v2(8.59,83.42) 8.59,84.21 8.56,84.23 8.56,85.12 4.14,89.54 4.14,94.22 4.95,95.03 12.19,95.03 v2(13.14,95.97)
PB6/TDI/RXD1: length 19.1
  TOP w0.35: R50.2 7.54,101.96 7.4,102.11 SW2.1 SW2.2
  TOP w0.4: U3.19 13,94.8 12.24,95.56 12.24,101.56 11.84,101.96 R50.2
PE0/TXD0: length 28
  TOP w0.3: 21.81,109.73 21.26,110.27 U8.25
  TOP w0.35: U3.30 16.18,87.65 v1(16.31,87.52)
  TOP w0.4: 21.81,109.73 21.81,107.08 v2(18.47,103.74)
  BOTTOM w0.4: v1(16.31,87.52) 16.91,87.52 18.47,89.08 v2(18.47,103.74)
PE1/RXD0: length 29.6
  TOP w0.4: U9.3 24.46,112.15 24.33,112.03 24.33,108.24 v2(17.48,101.38) ; v1(16.3,88.29) 16.29,88.3 U3.29
  BOTTOM w0.4: v2(17.48,101.38) 17.48,100.6 17.65,100.42 17.65,89.64 v1(16.3,88.29)
PE2/SCLK0: length 1.6
  TOP w0.4: v1(16.4,93.15) 16.06,93.5 U3.21
PHASEU:
  vias: v2(49.08,47.44) v2(49.08,45.94) v2(49.08,44.44) v2(50.58,44.44) v2(52.08,44.44) v2(52.08,42.94) v2(53.58,44.44) v2(53.58,42.94) v2(53.58,41.44) v2(53.56,39.28) v2(53.56,37.86) v2(55.08,44.44) v2(55.08,42.94) v2(55.08,41.44) v2(55.06,39.28) v2(55.06,37.86) v2(56.58,44.44) v2(56.58,42.94) v2(56.58,41.44) v2(56.56,39.28) v2(56.56,37.86) v2(58.08,44.44) v2(58.08,42.94) v2(58.08,41.44) v2(58.06,39.28) v2(58.06,37.86) v2(59.59,47.44) v2(59.59,45.94) v2(59.58,44.44) v2(61.09,47.44) v2(61.09,45.94) v2(61.08,44.44) v2(62.58,47.44) v2(62.58,45.94) v2(62.58,44.44) v2(64.08,47.44) v2(64.08,45.94) v2(64.08,44.44) v2(65.58,47.44) v2(65.58,45.94) v2(65.58,44.44) v2(67.08,47.44) v2(67.08,45.94) v2(67.08,44.44) v2(68.58,47.44) v2(68.58,45.94) v2(68.58,44.44) v2(70.08,47.44) v2(70.08,45.94) v2(70.08,44.44)
PHASEV:
  vias: v2(49.24,78.22) v2(49.24,76.72) v2(49.24,75.22) v2(50.74,75.22) v2(52.24,75.22) v2(52.24,73.72) v2(53.74,75.22) v2(53.74,73.72) v2(53.74,72.22) v2(53.71,70.12) v2(53.71,68.69) v2(55.24,75.22) v2(55.24,73.72) v2(55.24,72.22) v2(55.21,70.12) v2(55.21,68.69) v2(56.74,75.22) v2(56.74,73.72) v2(56.74,72.22) v2(56.71,70.12) v2(56.71,68.69) v2(58.24,75.22) v2(58.24,73.72) v2(58.24,72.22) v2(58.21,70.12) v2(58.21,68.69) v2(59.74,78.22) v2(59.74,76.72) v2(59.74,75.22) v2(61.24,78.22) v2(61.24,76.72) v2(61.24,75.22) v2(62.74,78.22) v2(62.74,76.72) v2(62.74,75.22) v2(64.24,78.22) v2(64.24,76.72) v2(64.24,75.22) v2(65.74,78.22) v2(65.74,76.72) v2(65.74,75.22) v2(67.24,78.22) v2(67.24,76.72) v2(67.24,75.22) v2(68.74,78.22) v2(68.74,76.72) v2(68.74,75.22) v2(70.24,78.22) v2(70.24,76.72) v2(70.24,75.22)
PHASEW:
  vias: v2(49.08,109.19) v2(49.08,107.69) v2(49.08,106.19) v2(50.58,106.19) v2(52.08,106.19) v2(52.08,104.69) v2(53.58,106.19) v2(53.58,104.69) v2(53.58,103.19) v2(53.61,101.1) v2(53.61,99.68) v2(55.08,106.19) v2(55.08,104.69) v2(55.08,103.19) v2(55.11,101.1) v2(55.11,99.68) v2(56.58,106.19) v2(56.58,104.69) v2(56.58,103.19) v2(56.61,101.1) v2(56.61,99.68) v2(58.08,106.19) v2(58.08,104.69) v2(58.08,103.19) v2(58.11,101.1) v2(58.11,99.68) v2(59.59,109.19) v2(59.59,107.69) v2(59.58,106.19) v2(61.09,109.19) v2(61.09,107.69) v2(61.08,106.19) v2(62.58,109.19) v2(62.58,107.69) v2(62.58,106.19) v2(64.08,109.19) v2(64.08,107.69) v2(64.08,106.19) v2(65.58,109.19) v2(65.58,107.69) v2(65.58,106.19) v2(67.08,109.19) v2(67.08,107.69) v2(67.08,106.19) v2(68.58,109.19) v2(68.58,107.69) v2(68.58,106.19) v2(70.08,109.19) v2(70.08,107.69) v2(70.08,106.19)
SOURCE: length 8.4
  TOP w0.35: 33.6,15.68 33.73,15.81 35.86,15.81 36.02,15.97
  TOP w0.4: C29.2 33.6,15.68 ; 36.02,15.97 36.02,18.43 35.62,18.83 R44.2
TCK/SWCLK: length 39.8
  TOP w0.4: J4.9 41.25,116.88 39.49,115.12 36.12,115.12 35.71,114.71 R34.2 34.78,113.58 34.44,113.25 34.44,109.86 32.79,108.21 26.8,108.21 16.33,97.75 16.33,96.35 16.08,96.1 U3.17
TMS/SWDIO: length 36.2
  TOP w0.4: U3.16 14.9,97.43 26.54,109.08 32.38,109.08 33.66,110.35 33.66,114.31 35.48,116.14 37.97,116.14 38.71,116.88 J4.7
U0: length 81.4
  TOP w0.4: U2.6 39.23,36.13 38.27,37.09 INH_U.1 33.4,40.49 33.4,67.45 32.38,68.46 32.38,81.49 34.09,83.19 34.09,91.37 33.26,92.2 U3.8
VREF: length 21.1
  TOP w0.4: U1.1 22.43,49.81 ; 22.43,49.81 22.43,50.17 22.14,50.46 U1.2 ; 22.43,49.81 22.43,49.5 v1(22.43,49.07) ; v1(19.69,55.85) 19.69,56.69 19.71,56.71 R16.1 18.85,57.64 18.82,57.61 R25.1
  TOP w0.508: R32.1 18.67,47.68 v1(18.65,47.7)
  BOTTOM w0.508: v1(19.69,55.85) 21.95,53.59 21.95,52.04 22.43,51.56 v1(22.43,49.07) 21.06,47.7 v1(18.65,47.7)
W0: length 28
  TOP w0.4: U6.6 40.36,98.03 38.12,95.79 38.12,95.79 INH_W.1 35.46,94.75 35.41,94.8 U3.12
X0: length 80.4
  TOP w0.4: U3.9 33.85,92.85 35.03,91.68 35.03,82.63 33.22,80.83 33.22,69.17 34.39,68 34.39,42.5 INL_U.1 40,36.89 44.85,36.89 44.88,36.88 U2.5
Y0: length 51.8
  TOP w0.4: U3.11 23.77,94.15 23.77,94.15 34.97,94.15 36.88,92.24 36.88,81.62 35.41,80.15 35.41,71.59 INL_V.1 39.26,67.74 U4.5
Z0: length 28.1
  TOP w0.4: U3.13 34.79,95.45 INL_W.1 37.08,97.88 37.99,98.79 39.19,98.79 39.2,98.78 U6.5
N11220086: length 5.2
  TOP w0.4: U3.14 24.63,96.1 R24.2 27.37,96.9 C19.1
N11227943: length 3.5
  TOP w0.4: 25.91,90.61 25.62,90.9 U3.6
N11232120: length 5.8
  TOP w0.4: U3.27 11.98,89.6 11.42,89.04
  TOP w0.5: Y1.1 11.4,89.02 11.42,89.04
N11232225: length 5.8
  TOP w0.4: 11.42,91.44 11.96,90.9 U3.25
  TOP w0.5: 11.42,91.44 11.4,91.42 Y1.3
N11232827: length 6.5
  TOP w0.4: U3.22 13.92,92.85 12.57,94.2 12.53,94.2 10.95,95.78 C17.1
N11233445: length 6.6
  TOP w0.4: U3.24 13.34,91.55 11.1,93.8 C12.1
N11251291: length 1.9
  TOP w0.4: D1.2 4.01,107.23 4.03,107.22 R3.1
N11255215: length 6.4
  TOP w0.5: R4.2 9.24,78.44 8.74,77.94 8.74,77.17 8.24,76.67 SW3.2
  TOP w0.508: R9.2 R4.2
N11983160: length 4.8
  TOP w0.35: R1.2 20.83,25.55 R6.1
N11983204: length 4.7
  TOP w0.35: R6.3 20.76,33.07 20.77,33.06 R14.1
N11990346: length 5.1
  TOP w0.4: R29.2 32.44,115.3 33.63,116.49 J4.3
N11990582: length 15.1
  TOP w0.4: R45.2 42.19,113.6 44.04,115.45 53.42,115.45 53.95,115.98 J4.19
N12027525: length 3.6
  TOP w0.35: C3.1 64.55,32.38 61.95,32.38 U2.14
N12027529: length 7.1
  TOP w0.35: U2.13 66.6,31.63 67.51,32.55 R15.1
N12027579: length 3
  TOP w0.4: R13.2 41.2,31.05 R8.1
N12027695: length 15.7
  TOP w0.4: IPH_U.1 40.83,42.07 43.67,42.07 43.97,41.77 R18.1 45.39,40.83 47.08,39.13 49.06,39.13 U2.2
N12027757: length 24.6
  TOP w0.4: v1(44.68,32.39) 47.72,32.39 47.73,32.38 49.06,32.38 U2.11 ; U2.4 47.15,37.63 47.14,37.63 v1(44.68,37.63) 43.97,38.34 C16.1 43.97,39.12 43.51,39.58 40.32,39.58 BPL_U.1
  BOTTOM w0.508: v1(44.68,32.39) v1(44.68,37.63)
N12027769: length 6.5
  TOP w0.4: U2.1 47.27,39.88 43.99,43.16 R21.1
N12027985: length 7
  TOP w0.4: U4.8 44.67,65.49 43.01,63.83 RT2.1
N12028197: length 3.5
  TOP w0.4: U4.14 64.57,63.24 C22.1
N12028205: length 7.5
  TOP w0.4: U4.13 67.2,62.49 67.77,63.05 R31.1
N12028339: length 15.1
  TOP w0.4: U4.2 46.33,69.99 44.82,71.49 R33.1 43.96,72.45 43.68,72.73 40.27,72.73 IPH_V.1
N12028369: length 14.4
  TOP w0.4: BPL_V.1 39.73,70.26 43.63,70.26 43.94,69.96 C26.1 44.48,68.49 U4.4
N12028389: length 6.6
  TOP w0.4: U4.1 47.05,70.74 43.94,73.85 R39.1
N12028721: length 3.6
  TOP w0.4: U6.14 63.36,94.28 64.09,95 C34.1
N12028725: length 7.1
  TOP w0.4: R46.1 67.59,94.65 66.47,93.53 U6.13
N12028855: length 13.2
  TOP w0.4: IPH_W.1 38.98,103.75 39.17,103.56 43.26,103.56 44.2,102.62 R49.1 45.31,102.55 46.83,101.03 U6.2
N12028877: length 13.4
  TOP w0.4: U6.4 45.69,99.53 45.26,99.96 C36.1 44.25,100.89 43.94,101.2 39.19,101.2 38.74,100.75 BPL_W.1
N12028909: length 6.2
  TOP w0.4: U6.1 47.17,101.78 44.2,104.76 R53.1
N12056627: length 9.1
  TOP w0.4: R13.1 42.37,33.18 42.37,34.23 42.77,34.63 U2.8
N12134803: length 3.7
  TOP w0.4: U1.7 21.69,53.71 21.92,53.93 21.92,56.14 22.4,56.63
N12134815: length 13.1
  TOP w0.4: U1.6 22.44,53.06 22.63,53.25 22.63,55.58 23.97,56.93 25.22,56.93 25.59,57.3 C1.2 25.59,60.25 R7.1 25.78,62.01 25.76,62.02 R11.2
N12135029: length 18.2
  TOP w0.35: D2.1 28.55,58.64
  TOP w0.4: v1(21.11,55.83) 21.11,56.43 21.13,56.45 R16.2 ; 28.56,58.91 28.56,58.65 28.55,58.64 27.23,57.31 27.2,57.31 26.08,56.19 24.59,56.19 24.18,55.78 R12.2 24.18,53.91 24.17,53.9 C5.1 23.31,52.86 v1(22.86,52.41) U1.5
  BOTTOM w0.508: v1(21.11,55.83) 22.86,54.08 v1(22.86,52.41)
N12135163: length 10.6
  TOP w0.4: R19.2 14.14,59.85 14.06,59.93 13.23,59.93 ; U1.8 14.98,53.71 14.53,54.16 14.53,54.18 13.97,54.74 C8.1 13.97,59.19 13.23,59.93 ; 13.23,59.93 R17.2
N12135175: length 11.3
  TOP w0.4: R20.2 11.76,61.4 11.78,61.38 R17.1 11.78,59.09 11.84,59.04 C8.2 11.84,56.85 13.24,55.45 13.24,54.36 14.53,53.06 U1.9
N12135393: length 20.4
  TOP w0.35: D3.1 8.76,58.15 10.18,56.73
  TOP w0.4: R25.2 16.2,56.63 16.18,56.61 v1(16.18,55.88) ; U1.10 14.34,52.41 13.56,53.18 v1(13.31,53.18) 12.23,53.18 C18.1
  TOP w0.508: 8.67,58.38 8.67,58.25 10.18,56.74 10.18,56.73 10.69,56.22 11.48,56.22 11.99,55.71 R23.2 12.02,54.92 C18.1
  BOTTOM w0.508: v1(13.31,53.18) 13.31,55.37 13.82,55.88 v1(16.18,55.88)
N12135507: length 9.9
  TOP w0.4: U1.14 14.98,49.81 14.5,49.33 14.5,46.61 C20.1
  TOP w0.508: C20.1 14.84,44.8 R26.2 16.31,44.13 16.33,44.15 R27.2
N12135519: length 10.1
  TOP w0.4: U1.13 14.41,50.46 13.36,49.41 13.36,47.74 12.7,47.08 C20.2 12.7,45.11 12.75,45.07 R26.1 12.75,43.13 12.8,43.08 R28.2
N12135733: length 19.7
  TOP w0.4: C25.1 13.16,50.97 13.29,51.1 v1(13.9,51.1) 14.33,51.1 14.33,51.11 U1.12
  TOP w0.508: D5.1 11.2,47.3 11.2,47.48 ; 11.2,47.48 11.5,47.48 12.01,47.99 12.01,48.98 R30.2 12.04,50.96 C25.1 ; 11.2,47.48 9.59,45.87 9.59,45.68 ; R32.2 17.24,47.72 v1(17.25,47.72)
  BOTTOM w0.508: v1(13.9,51.1) 13.9,48.89 15.07,47.72 v1(17.25,47.72)
N12135901: length 8.7
  TOP w0.4: U1.3 22.4,51.11 23.04,50.47 23.04,49.38 24.18,48.25 C28.1 R43.2 R37.1
N12173083: length 12.1
  TOP w0.35: U7.11 21.31,73.61 21.33,73.63 22.41,73.63 C41.1
  TOP w0.4: U7.11 18.6,73.61 18.31,73.32 v1(18.31,72.3) 18.36,72.3 18.38,72.31 U7.9 ; U7.5 14.32,72.96 v1(14.99,72.3)
  BOTTOM w0.4: v1(14.99,72.3) v1(18.31,72.3)
N12173113: length 11.7
  TOP w0.35: U7.14 20.52,75.56 20.8,75.84 20.8,77.39 ; U7.13 20.73,74.91 21.48,75.66 21.48,77.42
  TOP w0.4: 20.8,77.39 20.82,77.42 21.48,77.42 ; U7.2 14.79,74.91 15.18,75.3 R58.2
N12190188: length 4.2
  TOP w0.35: 42.71,26.58 42.63,26.5 R8.2
  TOP w0.508: R5.2 42.63,26.58 42.6,26.6 41.28,26.6
N12206798: length 5.5
  TOP w0.4: R38.1 34.52,17.1 C29.1 32.21,17.56 U5.1
N12206810: length 14.6
  TOP w0.4: R42.2 35.64,20.33 36.75,19.21 36.75,15.35 36.09,14.69 R38.2 33.78,13.67 C30.1 32.51,11.46 D6.1
N12206840: length 4.5
  TOP w0.4: U5.2 R44.1 R42.1
N12209410: length 12.2
  TOP w0.7: P1.6 P1.7 3.73,114.59 C37.1 3.71,112.63 R52.1
N12209768: length 20.4
  TOP w0.3: v1(14.66,112.02) 14.9,111.77 U8.8
  BOTTOM w0.4: v1(14.66,112.02) 11.68,112.02 9.73,113.98 7.26,113.98 5.85,115.39 5.85,115.51 5.25,116.11 5.25,119.99 5.97,120.71 8.89,120.71 P1.1
N12209854: length 3.8
  TOP w0.3: U8.26 21.26,110.77 21.79,111.31
  TOP w0.4: 21.79,111.31 21.79,111.75 22.19,112.15 U9.4
N12210084: length 5.8
  TOP w0.3: U8.9 14.64,111.27 14.43,111.06 14.43,108.11 14,107.68 R56.1
N12217120: length 6.4
  TOP w0.35: SW1.2 SW1.1
  TOP w0.4: SW1.2 64.87,120.14 64.58,120.43 R41.2
N12236869: length 2.1
  TOP w0.4: RT2.2 42.94,60.37 R36.2

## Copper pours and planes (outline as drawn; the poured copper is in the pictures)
+5V on TOP: 9.45,96.38 9.45,95.39 9.27,95.21 3.61,95.21 3.43,95.39 3.43,96.25 3.68,96.5 9.32,96.5
+5V on TOP: 12.9,88.22 12.9,86.17 12.42,85.68 2.9,85.68 2.72,85.86 2.72,86.77 2.9,86.95 11.43,86.95 12.75,88.27 12.85,88.27
+5V on TOP: 26.52,77.33 26.26,77.58 26.26,78.39 25.68,78.98 19.91,78.98 19.65,79.24 19.65,81.63 19.46,81.82 15.98,81.82 15.72,82.08 15.72,82.74 15.88,82.89 20.14,82.89 20.52,83.27 20.52,84.67 21.26,84.67 21.26,83.65 21.26,83.65 21.26,80.25 21.56,79.94 26.42,79.94 27.46,78.9 27.46,77.55 27.23,77.33
+5V on TOP: 30.1,12.07 30.1,10.12 29.87,9.89 13.67,9.89 13.65,9.9 8.31,9.9 8.03,10.18 8.03,12.45 8.46,12.89 24.84,12.89 25.65,12.07
+5V on BOTTOM: outline of 99 points within 0.36,9.94 38.3,123.66
GND on TOP: 68.17,9.61 67.92,9.86 67.92,14.18 68.83,15.1 82.32,15.1 84.63,17.41 84.63,31.48 78.2,31.48 78.19,31.47 74.51,31.47 74.01,31.98 74.01,36.1 74.25,36.33 78.3,36.33 78.3,36.33 84.63,36.33 84.63,62.31 75.56,62.31 75.56,62.32 74.58,62.32 74.15,62.75 74.15,66.82 74.16,66.82 74.5,67.17 78.25,67.17 78.25,67.17 84.63,67.17 84.63,92.31 83.61,93.33 74.8,93.33 74.05,94.08 74.05,97.88 74.37,98.21 88.42,98.21 88.98,97.65 88.98,10.42 88.16,9.61
GND on TOP: outline of 239 points within 0.23,9.76 37.61,123.86
GND on TOP: 21.42,75 21.42,74.8 23.21,74.8 23.8,75.38 25.44,75.38 25.73,75.68 25.73,78.01 25.34,78.41 22.32,78.41 21.99,78.08 21.99,75.57
GND on TOP: 11.4,92.25 7.74,92.25 7.5,92 7.5,90.85 7.72,90.62 10.87,90.62 11.05,90.45 12.34,90.45 12.54,90.24 12.34,90.04 11.12,90.04 10.84,89.76 7.67,89.76 7.57,89.66 7.57,89.65 7.47,89.55 7.47,88.53 7.69,88.31 11.45,88.31 12.19,89.05 12.37,89.05 12.56,88.86 12.56,88.69 11.43,87.56 7.38,87.56 6.68,88.26 6.68,92.39 7.01,92.72 11.55,92.72 12.44,91.84 12.44,91.63 12.34,91.54 12.11,91.54
GND on TOP: 29.21,65.2 24.97,65.2 24.51,64.74 24.51,62.28 24.08,61.85 21.19,61.85 20.78,62.25 20.78,63.12 21.11,63.45 23.04,63.45 23.29,63.7 23.29,65.49 20.52,68.26 20.52,70.72 21.26,71.46 27.05,71.46 31.47,67.04 31.47,55.96 31.29,55.79 29.54,55.79 29.29,56.04 29.29,56.45 30.38,57.54 30.38,64.93 30.11,65.2 29.22,65.2
GND on TOP: 12.52,123.83 72.44,123.83 72.72,123.55 72.72,120.07 72.26,119.62 71.4,119.62 71.02,120 71.02,122.51 70.43,123.1 63.63,123.1 62.71,122.18 56.9,122.18 54.53,119.82 32.99,119.82 32.59,120.23 32.59,121.8 32.21,122.18 29.46,122.18 29.1,121.81 29.1,113.79 28.6,113.29 23.42,113.29 22.73,113.98 22.73,118.45 21.62,119.57 19.1,119.57 17.65,121.01 12.6,121.01 12.52,121.09
GND on TOP: 30.3,91.45 30,91.75 27.25,91.75 27.15,91.65 27.15,91.47 27.57,91.05 27.57,84.91 25.65,82.99 21.77,82.99 21.64,82.86 21.64,80.45 21.92,80.17 26.97,80.17 28.02,79.13 28.02,73.72 28.22,73.52 28.65,73.52 28.93,73.8 28.93,82.46 30.3,83.83
GND on TOP: 16.36,103.03 16.36,100.01 15.57,99.22 14.68,99.22 14.12,99.78 14.12,104.02 13.77,104.38 12.45,104.38 12.04,104.78 12.04,105.06 11.66,105.44 7.98,105.44 7.59,105.82 7.59,107.12 6.83,107.88 6.83,113.37 7.26,113.8 9.22,113.8 9.32,113.7 9.32,111.97 9.4,111.9 10.34,111.9 10.62,111.62 10.62,108.14 12.29,106.46 18.87,106.46 19.08,106.26 19.08,105.75
GND on BOTTOM: 23.42,90.05 23.42,83.98 10.31,70.87 9.42,70.87 9.14,71.15 9.14,71.89 16.84,79.59 17.65,79.59 19.91,81.85 19.91,98.05 20.52,98.66 25.88,98.66 26.49,99.27 26.49,100.39 25.93,100.95 19.84,100.95 19.63,101.15 19.63,104.96 20.37,105.7 27.81,105.7 31.55,109.43 31.55,111.79 30.15,113.19 30.15,114.21 30.35,114.41 32.82,114.41 36.22,111.01 36.22,110.68 36.12,110.57 34.67,110.57 30.45,106.36 30.45,90.46 30.78,90.13 33.2,90.13 34.65,91.58 36.02,91.58 37.72,89.87 37.72,82.53 33.02,77.83 32.99,77.83 32.99,73.21 32.41,72.63 21.92,72.63 21.74,72.8 21.74,76.77 27.13,82.15 27.13,88.53 24.87,90.79 24.16,90.79
GND on BOTTOM: 46.91,9.2 41.14,14.98 28.91,14.98 25.59,18.3 17.12,18.3 16.33,17.51 16.33,14.31 15.74,13.71 9.36,13.71 7.92,15.15 7.92,17.43 13.13,22.64 13.13,24.29 9.88,27.54 9.88,35.49 11.05,36.66 35.23,36.66 38.05,33.84 39.53,33.84 40.36,34.67 40.36,45.07 40.41,45.12 40.41,77.58 42.14,79.31 42.14,82.18 41.81,82.51 35.56,82.51 35.08,82.99 35.08,91.56 39.61,91.56 40.51,92.46 40.51,105.22 41.78,106.49 41.78,110.24 32.94,119.08 32.94,122.74 33.96,123.76 72.03,123.76 72.25,123.54 72.25,119.35 71.93,119.03 49.23,119.03 45.18,114.99 45.18,39.33 43.92,38.06 43.92,31.91 45.18,30.65 45.18,25.08 44.7,24.6 41.07,24.6 40.36,23.88 40.36,22.69 47.9,15.15 82.09,15.15 84.23,17.28 88.54,17.28 88.98,16.85 88.98,10.48 87.71,9.2
GND on BOTTOM: 12.7,54.69 12.7,53.48 12.62,53.4 9.25,53.4 9.12,53.53 9.12,53.81 10.21,54.9 12.5,54.9
GND on BOTTOM: outline of 112 points within 3.87,35.89 38.25,73.08
GND on BOTTOM: outline of 104 points within 2.36,75.85 27.41,121.98
VBUS on TOP: 48.68,86.19 48.23,86.64 48.23,90.03 48.59,90.39 51.15,90.39 53.08,92.32 53.08,96.18 53.13,96.23 57.96,96.23 58.01,96.18 58.01,92.24 59.86,90.39 81.05,90.39 81.41,90.03 81.41,86.62 80.98,86.19
VBUS on TOP: 80.89,55.08 48.78,55.08 48.33,55.53 48.33,58.92 48.69,59.27 51.25,59.27 53.18,61.2 53.18,65.06 53.23,65.12 58.06,65.12 58.11,65.06 58.11,61.13 59.97,59.27 80.93,59.27 80.93,59.28 81.51,58.7 81.51,55.7
VBUS on TOP: 69.34,18.14 69.11,18.37 69.11,20.99 69.34,21.22 75.97,21.22 76.28,21.52 76.28,23.91 76,24.19 48.66,24.19 48.23,24.62 48.23,28.01 48.59,28.36 51.15,28.36 53.08,30.29 53.08,34.15 53.13,34.2 57.96,34.2 58.01,34.15 58.01,30.22 59.86,28.36 80.83,28.36 80.83,28.37 81.41,27.79 81.41,21.93 77.62,18.14
VBUS on BOTTOM: 78.82,19.06 73.66,24.22 48.79,24.22 48.44,24.56 48.44,24.67 48.44,24.67 48.44,34.15 48.64,34.35 84.33,34.35 84.33,54.98 48.82,54.98 48.47,55.32 48.47,55.43 48.46,55.43 48.46,64.91 48.67,65.11 84.33,65.11 84.33,86.07 48.76,86.07 48.42,86.41 48.42,86.52 48.41,86.52 48.41,96 48.62,96.2 88.57,96.2 88.93,95.84 88.93,21.45 88.52,21.04 80.8,21.04
VBUS IN on TOP: 47.65,15.15 47.65,10.27 46.79,9.41 38.81,9.41 38.48,9.74 38.48,11.34 42.29,15.15
ISENSE1 on TOP: 73.22,42.59 71.95,41.32 61.52,41.32 61.09,40.89 61.09,39.71 77,39.71 77.04,39.75 77.04,46.43 73.66,49.81 73.43,49.81 73.22,49.6
ISENSE2 on TOP: 73.38,73.33 72.11,72.06 61.67,72.06 61.24,71.62 61.24,70.51 77.19,70.51 77.19,77.16 73.82,80.54 73.59,80.54 73.38,80.33
ISENSE3 on TOP: 73.25,104.39 71.98,103.12 61.55,103.12 61.12,102.69 61.12,101.57 76.94,101.57 77.07,101.7 77.07,108.23 73.69,111.6 73.46,111.6 73.25,111.39
PHASEU on TOP: 61.13,35.83 61.13,33.97 61.21,33.9 62.81,33.9 63.62,34.71 67.94,34.71 67.94,36.51 67.41,37.04 64.47,37.04 63.94,36.51 60.45,36.51 58.9,38.06 58.52,38.06 58.49,38.04 58.49,37.38 58.52,37.35 58.9,37.35 60.3,35.95 61,35.95
PHASEU on TOP: 58.9,37.4 53.1,37.4 53,37.5 53,41.31 51.15,43.17 48.58,43.17 48.15,43.6 48.15,47.65 48.17,47.66 48.17,48.24 48.92,48.99 70.16,48.99 70.67,48.49 70.67,43.99 70.44,43.76 60.4,43.76 58.9,42.25
PHASEU on BOTTOM: 48.84,37.35 48.46,37.73 48.46,51.52 49,52.06 80.18,52.06 81.33,50.9 81.33,40.99 79.7,39.35 71.95,39.35 70.21,37.61 70.19,37.61 69.93,37.35
PHASEV on TOP: 61.26,66.74 61.26,64.88 61.33,64.81 62.93,64.81 63.75,65.62 68.25,65.62 68.25,67.6 67.84,68 64.52,68 63.94,67.42 60.58,67.42 59.03,68.97 58.64,68.97 58.62,68.95 58.62,68.29 58.64,68.26 59.03,68.26 60.42,66.86 61.13,66.86
PHASEV on TOP: 59.05,68.19 53.26,68.19 53.16,68.29 53.16,72.1 51.3,73.95 48.74,73.95 48.3,74.38 48.3,78.43 48.32,78.45 48.32,79.02 49.08,79.78 70.31,79.78 70.82,79.27 70.82,74.77 70.59,74.55 60.56,74.55 59.05,73.04
PHASEV on BOTTOM: 49,68.18 48.62,68.56 48.62,82.36 49.15,82.89 80.33,82.89 81.49,81.73 81.49,71.83 79.85,70.19 72.1,70.19 70.36,68.45 70.35,68.45 70.08,68.18
